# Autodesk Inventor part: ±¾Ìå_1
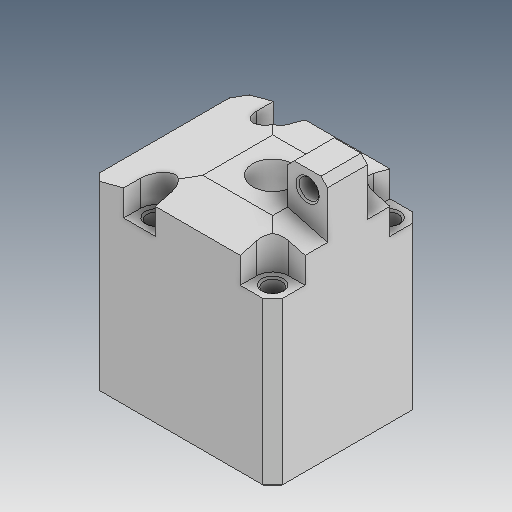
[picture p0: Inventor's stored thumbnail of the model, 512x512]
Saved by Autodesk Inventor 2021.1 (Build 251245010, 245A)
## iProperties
Created: 2019-04
Part Number: ±¾Ìå_1
Material: Ogólny
Document SubType Name: Modeling
Designer: user
Density: 1 g/cm^3
Appearance: Domyślna
Author: user
Revision Number: ÈÎºÎ
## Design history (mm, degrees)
feature "ÊäÈë1"
feature "ÊäÈë2"
feature "ÊäÈë3"
node "Bryła1"
node "Bryła2"
node "Bryła3"
